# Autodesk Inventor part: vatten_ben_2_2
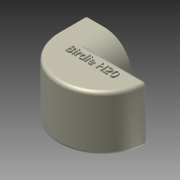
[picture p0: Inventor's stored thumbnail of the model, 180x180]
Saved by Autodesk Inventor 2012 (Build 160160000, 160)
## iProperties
Created: 2013-04
Part Number: vatten_ben_2_2
Material: Default
Document SubType Name: Modeling
Designer: soundwave
Density: 1 g/cm^3
Author: soundwave
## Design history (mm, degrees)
sketch "Sketch1"
  geometry: L1 (-7, 0)-(7, 0); L2 (-26, 0)-(-22, 0); L3 (-7, 0)-(7, 0); L4 (22, 0)-(26, 0); A1 r 22 centre (0, 0) between (-22, 0) and (22, 0); A2 r 7 centre (0, 0) between (-7, 0) and (7, 0); A3 r 26 centre (0, 0) between (-26, 0) and (26, 0); 2 further points
  constraints: 8 end point, 6 point on circle, 3 centre point, 3 coincident, 1 horizontal
  dimensions: "d9" = 4 radial gap between concentric circles of A1 A3; "d10" = 15 distance of L4.start L1.end; "d44" = 26 distance edge to line of A3 L1; "d45" = 52 distance of L4.end L2.start
extrude "Extrusion1" new body sketch "Sketch1" distance "d13" = 32; taper "d14" = 0 deg
sketch "Sketch2"
  geometry: L1 (0, 0)-(0, -32) reference; L2 (48, 0)-(4, 0) reference; L3 (4, -32)-(48, -32) reference; L4 (4, 0)-(19.038, 0); L5 (19.038, 0)-(19.038, -32); L6 (19.038, -32)-(4, -32); L7 (4, -32)-(4, 0); C1 r 7.5 at (11.5, -16); 1 further point
  constraints: 8 end point, 2 parallel, 1 centre point, 1 horizontal, 1 perpendicular, 1 point on line
  dimensions: "d15" = 15 diameter of C1; "d16" = 8.5 distance edge to line of C1 L2; "d17" = 8.5 distance edge to line of C1 L3 (derived); "d18" = 4 distance edge to line of C1 L1
sweep "Sweep1" dims "d22" = 0
  node "3D Sketch1"
sketch "Sketch23"
  geometry: L1 (52, 0)-(0, 0) reference; L2 (0, -32)-(52, -32) reference; L3 (0, 0)-(19, 0); L4 (19, 0)-(19, -32); L5 (19, -32)-(0, -32); L6 (0, -32)-(0, 0); C1 r 7.5 at (11.5, -16) reference; C2 r 7.5 at (11.5, -16); A1 r 16 centre (11.5, -16) between (0, -4.876) and (0, -27.124); A2 r 16 centre (11.5, -16) between (11.5, -32) and (11.5, 0); 1 further point
  constraints: 8 end point, 5 point on line, 4 point on circle, 3 centre point, 2 coincident, 2 parallel, 1 concentric, 1 horizontal, 1 perpendicular
extrude "Extrusion18" join sketch "Sketch23" distance "d191" = 10; taper "d192" = 0 deg
sketch "Sketch24"
  geometry: L1 (0, -32)-(0, -27.124) reference; L2 (11.5, -32)-(0, -32) reference; L3 (0, 0)-(11.5, 0) reference; L4 (0, -4.876)-(0, 0) reference; C1 r 7.5 at (11.5, -16) reference; A1 r 16 centre (11.5, -16) between (0, -4.876) and (0, -27.124) reference; A2 r 16 centre (11.5, -16) between (11.5, -32) and (11.5, 0) reference; 1 further point
extrude "Extrusion19" join sketch "Sketch24" distance "d197" = 5; taper "d198" = 0 deg
chamfer "Chamfer25" distance "d199" = 7; stored, may be unused: second distance "d200" = 2, angle "d201" = 45 deg
chamfer "Chamfer26" distance "d202" = 7; stored, may be unused: second distance "d203" = 2, angle "d204" = 45 deg
fillet "Fillet38" dims "d205" = 7
fillet "Fillet39" dims "d206" = 7
fillet "Fillet40" dims "d207" = 2
fillet "Fillet41" dims "d208" = 5
fillet "Fillet42" dims "d209" = 1
sketch "Sketch25"
  geometry: L1 (-14.28, -3.699)-(23.095, -3.699); L2 (23.095, -3.699)-(23.095, -15); L3 (23.095, -15)-(-14.28, -15); L4 (-14.28, -15)-(-14.28, -3.699)
  constraints: 2 other
extrude "Extrusion20" join sketch "Sketch25" distance "d210" = 1; taper "d211" = 0 deg
body "Solid1"
other parameters: "d59" = 32, "d190" = 32
